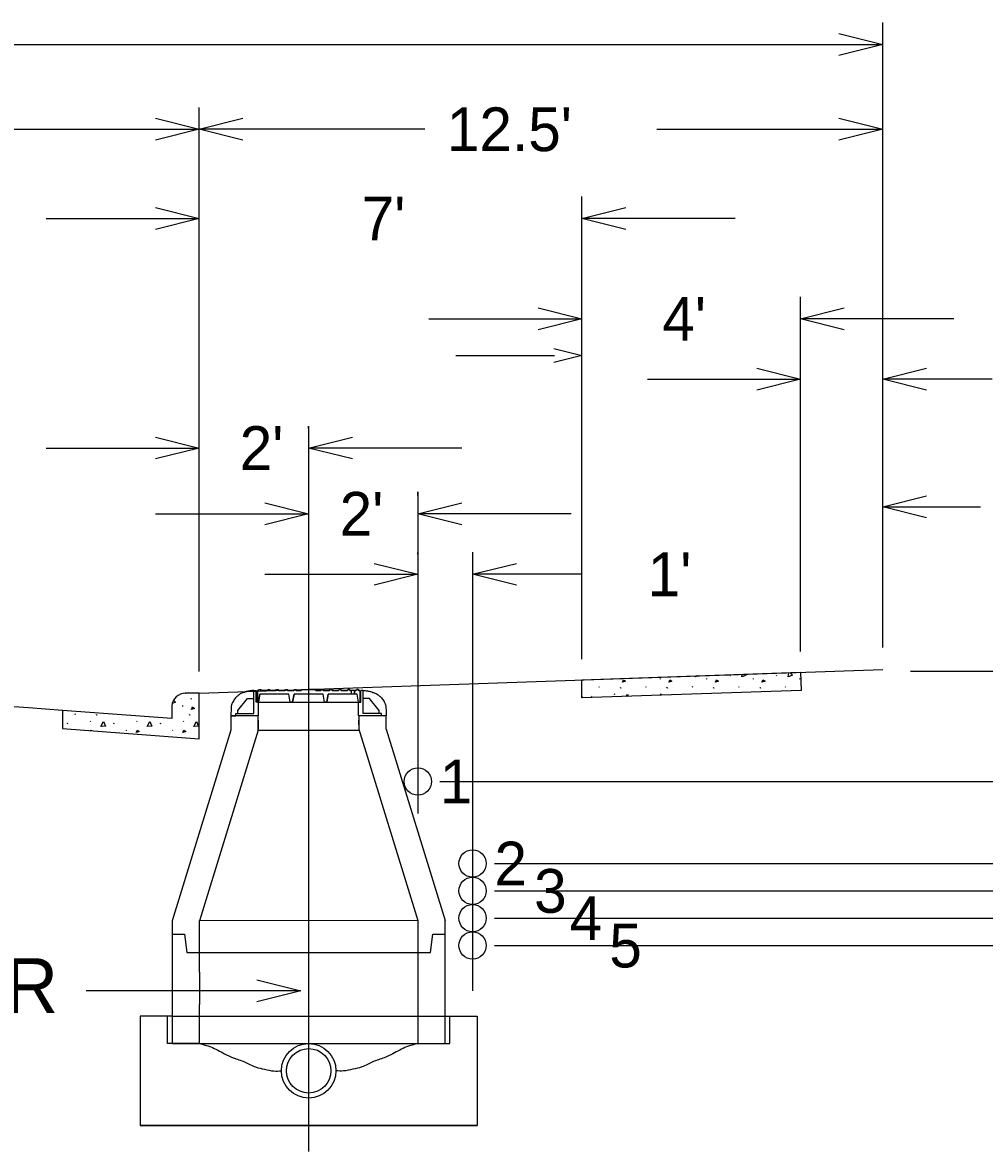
# Model space of a CAD drawing. Extents: x 524397 to 525117, y 3701341 to 3701821.
# Drawn here: x 524572.41 to 524607.59, y 3701671.5 to 3701712.8 of the extents above; entities that cross this region are included whole.
import ezdxf

# ---------------------------------------------------------------- set-up
doc = ezdxf.new("R2010")
doc.units = 0
doc.layers.add('Level 11', color=7, linetype='Continuous')

msp = doc.modelspace()

# ---------------------------------------------------------------- linework, layer by layer
at = {"layer": 'Level 11'}
for p, q in [((524603.871, 3701689.934), (524603.871, 3701712.797)), ((524542.077, 3701711.996), (524603.871, 3701711.996)), ((524578.871, 3701689.06), (524578.871, 3701709.694)), ((524603.871, 3701689.934), (524603.871, 3701709.694)), ((524536.524, 3701708.893), (524578.871, 3701708.893)), ((524587.129, 3701708.893), (524578.871, 3701708.893)), ((524595.613, 3701708.893), (524603.871, 3701708.893)), ((524578.871, 3701689.06), (524578.871, 3701706.43)), ((524578.871, 3701689.861), (524578.871, 3701706.43)), ((524592.871, 3701689.514), (524592.871, 3701706.43)), ((524577.27, 3701706.029), (524578.871, 3701705.629)), ((524577.27, 3701706.029), (524578.871, 3701705.629)), ((524592.871, 3701705.629), (524594.472, 3701706.029)), ((524573.267, 3701705.629), (524578.871, 3701705.629)), ((524578.871, 3701705.629), (524577.27, 3701705.229)), ((524578.871, 3701705.629), (524577.27, 3701705.229)), ((524598.475, 3701705.629), (524592.871, 3701705.629)), ((524594.472, 3701705.229), (524592.871, 3701705.629)), ((524592.871, 3701689.514), (524592.871, 3701702.759)), ((524600.866, 3701689.793), (524600.866, 3701702.759)), ((524591.27, 3701702.359), (524592.871, 3701701.959)), ((524600.866, 3701701.959), (524602.467, 3701702.359)), ((524587.267, 3701701.959), (524592.871, 3701701.959)), ((524592.871, 3701701.959), (524591.27, 3701701.559)), ((524606.47, 3701701.959), (524600.866, 3701701.959)), ((524602.467, 3701701.559), (524600.866, 3701701.959)), ((524591.84, 3701700.877), (524592.871, 3701700.619)), ((524588.262, 3701700.619), (524591.871, 3701700.619)), ((524592.871, 3701700.619), (524591.84, 3701700.362)), ((524600.866, 3701689.793), (524600.866, 3701700.554)), ((524603.871, 3701690.379), (524603.871, 3701700.554)), ((524599.265, 3701700.154), (524600.866, 3701699.754)), ((524603.871, 3701699.754), (524605.472, 3701700.154)), ((524595.263, 3701699.754), (524600.866, 3701699.754)), ((524600.866, 3701699.754), (524599.265, 3701699.354)), ((524607.874, 3701699.754), (524603.871, 3701699.754)), ((524605.472, 3701699.354), (524603.871, 3701699.754)), ((524578.871, 3701689.861), (524578.871, 3701698.033)), ((524582.871, 3701698.034), (524582.871, 3701671.502)), ((524582.871, 3701697.942), (524582.871, 3701698.033)), ((524577.27, 3701697.633), (524578.871, 3701697.233)), ((524582.871, 3701697.233), (524584.472, 3701697.633)), ((524573.267, 3701697.233), (524578.871, 3701697.233)), ((524578.871, 3701697.233), (524577.27, 3701696.833)), ((524588.475, 3701697.233), (524582.871, 3701697.233)), ((524584.472, 3701696.833), (524582.871, 3701697.233)), ((524586.871, 3701695.628), (524586.871, 3701695.061)), ((524586.871, 3701695.628), (524586.871, 3701683.862)), ((524586.871, 3701695.502), (524586.871, 3701695.627)), ((524603.875, 3701695.082), (524605.476, 3701695.483)), ((524581.27, 3701695.227), (524582.871, 3701694.827)), ((524586.871, 3701694.827), (524588.472, 3701695.227)), ((524603.875, 3701695.082), (524607.443, 3701695.082)), ((524605.476, 3701694.682), (524603.875, 3701695.082)), ((524577.267, 3701694.827), (524582.871, 3701694.827)), ((524582.871, 3701694.827), (524581.27, 3701694.427)), ((524592.475, 3701694.827), (524586.871, 3701694.827)), ((524588.472, 3701694.427), (524586.871, 3701694.827)), ((524582.871, 3701694.141), (524582.871, 3701694.027)), ((524586.871, 3701693.342), (524586.871, 3701693.414)), ((524588.871, 3701693.428), (524588.871, 3701677.373)), ((524585.27, 3701693.014), (524586.871, 3701692.613)), ((524588.871, 3701692.613), (524590.472, 3701693.014)), ((524581.267, 3701692.613), (524586.871, 3701692.613)), ((524586.871, 3701692.613), (524585.27, 3701692.213)), ((524588.871, 3701692.627), (524588.871, 3701691.813)), ((524592.874, 3701692.613), (524588.871, 3701692.613)), ((524590.472, 3701692.213), (524588.871, 3701692.613)), ((524578.871, 3701688.26), (524603.871, 3701689.133)), ((524592.871, 3701688.749), (524600.866, 3701689.029)), ((524595.726, 3701688.806), (524595.73, 3701688.774)), ((524597.428, 3701688.806), (524597.431, 3701688.774)), ((524598.285, 3701688.895), (524598.299, 3701688.927)), ((524599.129, 3701688.806), (524599.133, 3701688.774)), ((524599.986, 3701688.895), (524600.001, 3701688.927)), ((524600.831, 3701688.806), (524600.834, 3701688.774)), ((524600.866, 3701689.029), (524600.889, 3701688.369)), ((524610.833, 3701689.063), (524604.887, 3701689.063)), ((524581.039, 3701688.358), (524581.054, 3701688.4)), ((524581.039, 3701688.358), (524581.054, 3701688.4)), ((524581.054, 3701688.4), (524581.117, 3701688.4)), ((524581.054, 3701688.4), (524581.117, 3701688.4)), ((524581.132, 3701688.358), (524581.117, 3701688.4)), ((524581.117, 3701688.4), (524581.132, 3701688.358)), ((524581.363, 3701688.358), (524581.378, 3701688.4)), ((524581.363, 3701688.358), (524581.378, 3701688.4)), ((524581.378, 3701688.4), (524581.438, 3701688.4)), ((524581.378, 3701688.4), (524581.438, 3701688.4)), ((524581.453, 3701688.358), (524581.438, 3701688.4)), ((524581.438, 3701688.4), (524581.453, 3701688.358)), ((524581.679, 3701688.358), (524581.694, 3701688.4)), ((524581.679, 3701688.358), (524581.694, 3701688.4)), ((524581.694, 3701688.4), (524581.762, 3701688.4)), ((524581.694, 3701688.4), (524581.762, 3701688.4)), ((524581.777, 3701688.358), (524581.762, 3701688.4)), ((524581.762, 3701688.4), (524581.777, 3701688.358)), ((524582.006, 3701688.358), (524582.022, 3701688.4)), ((524582.006, 3701688.358), (524582.022, 3701688.4)), ((524582.022, 3701688.4), (524582.087, 3701688.4)), ((524582.022, 3701688.4), (524582.087, 3701688.4)), ((524582.102, 3701688.358), (524582.087, 3701688.4)), ((524582.087, 3701688.4), (524582.102, 3701688.358)), ((524582.329, 3701688.358), (524582.344, 3701688.4)), ((524582.329, 3701688.358), (524582.344, 3701688.4)), ((524582.344, 3701688.4), (524582.402, 3701688.4)), ((524582.344, 3701688.4), (524582.402, 3701688.4)), ((524582.418, 3701688.358), (524582.402, 3701688.4)), ((524582.402, 3701688.4), (524582.418, 3701688.358)), ((524582.604, 3701688.358), (524582.62, 3701688.4)), ((524582.604, 3701688.358), (524582.62, 3701688.4)), ((524582.62, 3701688.4), (524582.87, 3701688.4)), ((524582.62, 3701688.4), (524583.122, 3701688.4)), ((524583.122, 3701688.4), (524582.87, 3701688.4)), ((524583.137, 3701688.358), (524583.122, 3701688.4)), ((524583.122, 3701688.4), (524583.137, 3701688.358)), ((524583.324, 3701688.358), (524583.339, 3701688.4)), ((524583.324, 3701688.358), (524583.339, 3701688.4)), ((524583.397, 3701688.4), (524583.339, 3701688.4)), ((524583.339, 3701688.4), (524583.397, 3701688.4)), ((524583.412, 3701688.358), (524583.397, 3701688.4)), ((524583.397, 3701688.4), (524583.412, 3701688.358)), ((524583.639, 3701688.358), (524583.655, 3701688.4)), ((524583.639, 3701688.358), (524583.655, 3701688.4)), ((524583.72, 3701688.4), (524583.655, 3701688.4)), ((524583.655, 3701688.4), (524583.72, 3701688.4)), ((524583.735, 3701688.358), (524583.72, 3701688.4)), ((524583.72, 3701688.4), (524583.735, 3701688.358)), ((524583.964, 3701688.358), (524583.979, 3701688.4)), ((524583.964, 3701688.358), (524583.979, 3701688.4)), ((524584.047, 3701688.4), (524583.979, 3701688.4)), ((524583.979, 3701688.4), (524584.047, 3701688.4)), ((524584.062, 3701688.358), (524584.047, 3701688.4)), ((524584.047, 3701688.4), (524584.062, 3701688.358)), ((524584.289, 3701688.358), (524584.303, 3701688.4)), ((524584.289, 3701688.358), (524584.303, 3701688.4)), ((524584.363, 3701688.4), (524584.303, 3701688.4)), ((524584.303, 3701688.4), (524584.363, 3701688.4)), ((524584.378, 3701688.358), (524584.363, 3701688.4)), ((524584.363, 3701688.4), (524584.378, 3701688.358)), ((524584.609, 3701688.358), (524584.625, 3701688.4)), ((524584.609, 3701688.358), (524584.625, 3701688.4)), ((524584.687, 3701688.4), (524584.625, 3701688.4)), ((524584.625, 3701688.4), (524584.687, 3701688.4)), ((524584.702, 3701688.358), (524584.687, 3701688.4)), ((524584.687, 3701688.4), (524584.702, 3701688.358)), ((524592.871, 3701688.089), (524592.871, 3701688.749)), ((524593.504, 3701688.483), (524593.518, 3701688.515)), ((524594.027, 3701688.79), (524594.028, 3701688.774)), ((524594.267, 3701688.483), (524594.281, 3701688.462)), ((524594.281, 3701688.475), (524594.296, 3701688.454)), ((524595.205, 3701688.483), (524595.219, 3701688.515)), ((524595.969, 3701688.483), (524595.983, 3701688.462)), ((524595.983, 3701688.475), (524595.997, 3701688.454)), ((524596.907, 3701688.483), (524596.921, 3701688.515)), ((524597.67, 3701688.483), (524597.684, 3701688.462)), ((524597.684, 3701688.475), (524597.699, 3701688.454)), ((524598.608, 3701688.483), (524598.622, 3701688.515)), ((524599.372, 3701688.483), (524599.386, 3701688.462)), ((524599.386, 3701688.475), (524599.4, 3701688.454)), ((524600.31, 3701688.483), (524600.324, 3701688.515)), ((524578.871, 3701688.26), (524578.358, 3701688.26)), ((524578.358, 3701688.26), (524578.371, 3701688.26)), ((524578.871, 3701688.26), (524578.358, 3701688.26)), ((524578.358, 3701688.26), (524578.371, 3701688.26)), ((524578.577, 3701688.047), (524578.591, 3701688.078)), ((524578.577, 3701688.047), (524578.591, 3701688.078)), ((524578.871, 3701686.598), (524578.871, 3701688.26)), ((524578.871, 3701686.598), (524578.871, 3701688.26)), ((524580.289, 3701687.63), (524580.639, 3701688.067)), ((524580.639, 3701688.067), (524580.872, 3701688.067)), ((524580.872, 3701688.358), (524580.872, 3701688.358)), ((524580.872, 3701688.358), (524580.955, 3701688.358)), ((524580.872, 3701688.067), (524580.872, 3701688.358)), ((524580.872, 3701687.525), (524580.872, 3701688.067)), ((524580.955, 3701687.942), (524580.955, 3701688.358)), ((524580.997, 3701688.358), (524580.997, 3701687.942)), ((524581.039, 3701688.358), (524580.997, 3701688.358)), ((524580.997, 3701688.358), (524581.039, 3701688.358)), ((524580.997, 3701687.942), (524580.997, 3701688.358)), ((524581.038, 3701687.942), (524581.09, 3701688.233)), ((524581.09, 3701688.233), (524581.038, 3701687.942)), ((524582.153, 3701688.233), (524581.09, 3701688.233)), ((524582.153, 3701688.233), (524581.09, 3701688.233)), ((524581.363, 3701688.358), (524581.132, 3701688.358)), ((524581.132, 3701688.358), (524581.363, 3701688.358)), ((524581.679, 3701688.358), (524581.453, 3701688.358)), ((524581.453, 3701688.358), (524581.679, 3701688.358)), ((524582.006, 3701688.358), (524581.777, 3701688.358)), ((524581.777, 3701688.358), (524582.006, 3701688.358)), ((524582.329, 3701688.358), (524582.102, 3701688.358)), ((524582.102, 3701688.358), (524582.329, 3701688.358)), ((524582.204, 3701687.942), (524582.153, 3701688.233)), ((524582.204, 3701687.942), (524582.153, 3701688.233)), ((524582.288, 3701687.942), (524582.339, 3701688.233)), ((524582.339, 3701688.233), (524582.288, 3701687.942)), ((524583.402, 3701688.233), (524582.339, 3701688.233)), ((524583.402, 3701688.233), (524582.339, 3701688.233)), ((524582.604, 3701688.358), (524582.418, 3701688.358)), ((524582.418, 3701688.358), (524582.604, 3701688.358)), ((524583.324, 3701688.358), (524583.137, 3701688.358)), ((524583.137, 3701688.358), (524583.324, 3701688.358)), ((524583.454, 3701687.942), (524583.402, 3701688.233)), ((524583.454, 3701687.942), (524583.402, 3701688.233)), ((524583.639, 3701688.358), (524583.412, 3701688.358)), ((524583.412, 3701688.358), (524583.639, 3701688.358)), ((524583.537, 3701687.942), (524583.588, 3701688.233)), ((524583.588, 3701688.233), (524583.537, 3701687.942)), ((524584.651, 3701688.233), (524583.588, 3701688.233)), ((524584.432, 3701688.233), (524583.588, 3701688.233)), ((524583.964, 3701688.358), (524583.735, 3701688.358)), ((524583.735, 3701688.358), (524583.964, 3701688.358)), ((524584.289, 3701688.358), (524584.062, 3701688.358)), ((524584.062, 3701688.358), (524584.289, 3701688.358)), ((524584.609, 3701688.358), (524584.378, 3701688.358)), ((524584.378, 3701688.358), (524584.432, 3701688.358)), ((524584.432, 3701688.358), (524584.432, 3701688.233)), ((524584.432, 3701688.358), (524584.432, 3701688.233)), ((524584.557, 3701688.358), (524584.557, 3701688.233)), ((524584.557, 3701688.358), (524584.609, 3701688.358)), ((524584.557, 3701688.233), (524584.557, 3701688.358)), ((524584.651, 3701688.233), (524584.557, 3701688.233)), ((524584.703, 3701687.942), (524584.651, 3701688.233)), ((524584.703, 3701687.942), (524584.651, 3701688.233)), ((524584.744, 3701688.358), (524584.702, 3701688.358)), ((524584.702, 3701688.358), (524584.744, 3701688.358)), ((524584.744, 3701688.358), (524584.744, 3701687.942)), ((524584.744, 3701688.358), (524584.744, 3701687.942)), ((524584.786, 3701687.942), (524584.786, 3701688.358)), ((524584.869, 3701688.358), (524584.786, 3701688.358)), ((524584.869, 3701688.067), (524584.869, 3701688.358)), ((524584.869, 3701687.525), (524584.869, 3701688.067)), ((524585.102, 3701688.067), (524584.869, 3701688.067)), ((524585.452, 3701687.63), (524585.102, 3701688.067)), ((524600.889, 3701688.369), (524592.871, 3701688.089)), ((524593.216, 3701688.138), (524593.23, 3701688.17)), ((524594.058, 3701688.22), (524594.072, 3701688.252)), ((524594.927, 3701688.161), (524594.932, 3701688.17)), ((524595.759, 3701688.22), (524595.773, 3701688.252)), ((524597.474, 3701688.25), (524597.475, 3701688.252)), ((524577.871, 3701687.335), (524573.871, 3701687.637)), ((524573.871, 3701687.637), (524573.871, 3701686.976)), ((524577.871, 3701687.335), (524573.871, 3701687.637)), ((524573.871, 3701687.637), (524573.871, 3701686.976)), ((524577.871, 3701687.798), (524577.871, 3701687.335)), ((524577.871, 3701687.798), (524577.871, 3701687.335)), ((524578.26, 3701687.812), (524578.263, 3701687.78)), ((524578.26, 3701687.812), (524578.263, 3701687.78)), ((524580.289, 3701687.525), (524580.289, 3701687.63)), ((524581.038, 3701687.942), (524580.955, 3701687.942)), ((524580.997, 3701687.942), (524584.744, 3701687.942)), ((524581.038, 3701687.942), (524580.997, 3701687.942)), ((524581.038, 3701687.442), (524581.038, 3701687.942)), ((524582.288, 3701687.942), (524582.204, 3701687.942)), ((524583.537, 3701687.942), (524583.454, 3701687.942)), ((524584.703, 3701687.442), (524584.703, 3701687.942)), ((524584.703, 3701687.942), (524584.786, 3701687.942)), ((524584.744, 3701687.942), (524584.703, 3701687.942)), ((524585.452, 3701687.525), (524585.452, 3701687.63)), ((524574.048, 3701687.144), (524574.062, 3701687.176)), ((524574.048, 3701687.144), (524574.062, 3701687.176)), ((524574.336, 3701687.489), (524574.35, 3701687.521)), ((524574.336, 3701687.489), (524574.35, 3701687.521)), ((524574.89, 3701687.226), (524574.904, 3701687.258)), ((524574.89, 3701687.226), (524574.904, 3701687.258)), ((524575.099, 3701687.489), (524575.113, 3701687.468)), ((524575.099, 3701687.489), (524575.113, 3701687.468)), ((524575.113, 3701687.481), (524575.128, 3701687.459)), ((524575.113, 3701687.481), (524575.128, 3701687.459)), ((524575.749, 3701687.144), (524575.764, 3701687.176)), ((524575.749, 3701687.144), (524575.764, 3701687.176)), ((524576.591, 3701687.226), (524576.605, 3701687.258)), ((524576.591, 3701687.226), (524576.605, 3701687.258)), ((524577.451, 3701687.144), (524577.465, 3701687.176)), ((524577.451, 3701687.144), (524577.465, 3701687.176)), ((524578.293, 3701687.226), (524578.307, 3701687.258)), ((524578.293, 3701687.226), (524578.307, 3701687.258)), ((524578.502, 3701687.489), (524578.516, 3701687.468)), ((524578.502, 3701687.489), (524578.516, 3701687.468)), ((524578.516, 3701687.481), (524578.531, 3701687.459)), ((524578.516, 3701687.481), (524578.531, 3701687.459)), ((524580.028, 3701687.442), (524580.028, 3701686.909)), ((524581.038, 3701687.442), (524580.028, 3701687.442)), ((524580.028, 3701687.442), (524580.205, 3701687.442)), ((524580.205, 3701687.442), (524580.205, 3701687.525)), ((524580.205, 3701687.525), (524580.289, 3701687.525)), ((524580.289, 3701687.525), (524580.872, 3701687.525)), ((524581.028, 3701686.909), (524581.028, 3701687.442)), ((524581.028, 3701687.276), (524581.028, 3701686.949)), ((524585.713, 3701687.442), (524584.703, 3701687.442)), ((524584.713, 3701687.442), (524584.713, 3701686.943)), ((524584.713, 3701687.109), (524584.713, 3701687.283)), ((524585.713, 3701687.442), (524584.714, 3701687.442)), ((524585.452, 3701687.525), (524584.869, 3701687.525)), ((524585.535, 3701687.525), (524585.452, 3701687.525)), ((524585.535, 3701687.442), (524585.535, 3701687.525)), ((524585.713, 3701687.442), (524585.535, 3701687.442)), ((524585.713, 3701686.943), (524585.713, 3701687.442)), ((524573.871, 3701686.976), (524578.871, 3701686.598)), ((524573.871, 3701686.976), (524578.871, 3701686.598)), ((524576.193, 3701686.917), (524576.208, 3701686.895)), ((524576.193, 3701686.917), (524576.208, 3701686.895)), ((524580.028, 3701686.909), (524577.878, 3701679.942)), ((524577.895, 3701686.917), (524577.909, 3701686.895)), ((524577.895, 3701686.917), (524577.909, 3701686.895)), ((524581.028, 3701686.909), (524578.877, 3701679.942)), ((524581.028, 3701686.909), (524584.713, 3701686.909)), ((524584.713, 3701686.943), (524586.873, 3701679.947)), ((524585.713, 3701686.943), (524587.872, 3701679.947)), ((524587.671, 3701685.033), (524617.96, 3701685.033)), ((524589.671, 3701682.033), (524620.485, 3701682.033)), ((524589.671, 3701681.033), (524622.729, 3701681.033)), ((524577.878, 3701679.942), (524577.878, 3701678.781)), ((524586.873, 3701679.946), (524578.877, 3701679.942)), ((524578.877, 3701678.781), (524578.877, 3701679.942)), ((524586.873, 3701679.947), (524586.873, 3701678.781)), ((524586.873, 3701679.947), (524586.873, 3701679.447)), ((524587.872, 3701679.447), (524587.872, 3701679.947)), ((524587.872, 3701679.447), (524587.872, 3701679.947)), ((524589.671, 3701680.033), (524624.974, 3701680.033)), ((524577.878, 3701679.649), (524577.878, 3701679.447)), ((524577.878, 3701679.447), (524578.336, 3701679.447)), ((524577.878, 3701679.447), (524578.336, 3701679.447)), ((524577.878, 3701679.447), (524577.878, 3701678.06)), ((524578.336, 3701679.447), (524578.419, 3701678.781)), ((524578.336, 3701679.447), (524578.419, 3701678.781)), ((524578.877, 3701679.447), (524578.877, 3701679.649)), ((524578.877, 3701678.06), (524578.877, 3701679.447)), ((524586.873, 3701679.649), (524586.873, 3701679.447)), ((524586.873, 3701679.649), (524586.873, 3701679.447)), ((524586.873, 3701679.447), (524586.873, 3701675.449)), ((524586.873, 3701679.447), (524586.873, 3701675.449)), ((524587.331, 3701678.781), (524587.414, 3701679.447)), ((524587.331, 3701678.781), (524587.414, 3701679.447)), ((524587.414, 3701679.447), (524587.872, 3701679.447)), ((524587.414, 3701679.447), (524587.872, 3701679.447)), ((524587.414, 3701679.447), (524587.872, 3701679.447)), ((524587.872, 3701675.449), (524587.872, 3701679.649)), ((524587.872, 3701678.781), (524587.872, 3701679.447)), ((524577.878, 3701679.059), (524577.878, 3701675.449)), ((524589.671, 3701679.033), (524627.499, 3701679.033)), ((524578.419, 3701678.781), (524578.877, 3701678.781)), ((524578.419, 3701678.781), (524578.877, 3701678.781)), ((524578.877, 3701678.781), (524586.873, 3701678.781)), ((524578.877, 3701678.781), (524586.873, 3701678.781)), ((524586.873, 3701678.781), (524587.331, 3701678.781)), ((524586.873, 3701678.781), (524587.331, 3701678.781)), ((524578.877, 3701678.06), (524578.877, 3701676.875)), ((524580.981, 3701677.775), (524582.582, 3701677.375)), ((524582.582, 3701677.375), (524574.74, 3701677.375)), ((524582.582, 3701677.375), (524580.981, 3701676.975)), ((524578.877, 3701675.449), (524578.877, 3701676.875)), ((524577.878, 3701676.449), (524576.712, 3701676.449)), ((524576.712, 3701676.449), (524576.712, 3701672.451)), ((524577.712, 3701675.449), (524577.712, 3701676.449)), ((524577.878, 3701676.449), (524587.872, 3701676.449)), ((524587.872, 3701676.449), (524589.038, 3701676.449)), ((524588.039, 3701675.449), (524588.039, 3701676.449)), ((524589.038, 3701676.449), (524589.038, 3701672.451)), ((524577.878, 3701675.449), (524577.712, 3701675.449)), ((524577.878, 3701675.449), (524577.712, 3701675.449)), ((524577.878, 3701675.449), (524578.877, 3701675.449)), ((524578.877, 3701675.449), (524577.878, 3701675.449)), ((524578.877, 3701675.449), (524577.878, 3701675.449)), ((524578.877, 3701675.449), (524586.873, 3701675.449)), ((524586.873, 3701675.449), (524587.872, 3701675.449)), ((524586.873, 3701675.449), (524587.872, 3701675.449)), ((524587.872, 3701675.449), (524588.039, 3701675.449)), ((524589.038, 3701672.451), (524576.712, 3701672.451)), ((524576.712, 3701672.451), (524589.038, 3701672.451))]:
    msp.add_line(p, q, dxfattribs=at)
for points in [[(524602.27, 3701712.397), (524603.871, 3701711.996), (524602.27, 3701711.596)], [(524577.27, 3701709.294), (524578.871, 3701708.893), (524577.27, 3701708.493)], [(524580.472, 3701708.493), (524578.871, 3701708.893), (524580.472, 3701709.294)], [(524602.27, 3701709.294), (524603.871, 3701708.893), (524602.27, 3701708.493)], [(524597.015, 3701688.859), (524597.02, 3701688.894)], [(524597.099, 3701688.897), (524597.019, 3701688.86)], [(524598.717, 3701688.859), (524598.73, 3701688.954)], [(524598.845, 3701688.958), (524598.872, 3701688.93), (524598.72, 3701688.86)], [(524600.418, 3701688.859), (524600.44, 3701689.014)], [(524600.491, 3701689.015), (524600.574, 3701688.93), (524600.422, 3701688.86)], [(524594.349, 3701688.668), (524594.392, 3701688.757), (524594.463, 3701688.703), (524594.349, 3701688.668)], [(524596.051, 3701688.668), (524596.093, 3701688.757), (524596.164, 3701688.703), (524596.051, 3701688.668)], [(524597.752, 3701688.668), (524597.795, 3701688.757), (524597.866, 3701688.703), (524597.752, 3701688.668)], [(524599.454, 3701688.668), (524599.496, 3701688.757), (524599.567, 3701688.703), (524599.454, 3701688.668)], [(524577.935, 3701688.006), (524578.003, 3701687.936), (524577.898, 3701687.887)], [(524577.935, 3701688.006), (524578.003, 3701687.936), (524577.898, 3701687.887)], [(524592.871, 3701688.137), (524592.892, 3701688.09)], [(524594.492, 3701688.146), (524594.534, 3701688.223), (524594.567, 3701688.148)], [(524596.226, 3701688.206), (524596.235, 3701688.223), (524596.243, 3701688.207)], [(524578.584, 3701687.674), (524578.627, 3701687.762), (524578.698, 3701687.709), (524578.584, 3701687.674)], [(524578.584, 3701687.674), (524578.627, 3701687.762), (524578.698, 3701687.709), (524578.584, 3701687.674)], [(524575.27, 3701687.048), (524575.366, 3701687.229), (524575.44, 3701687.062), (524575.273, 3701687.048)], [(524575.27, 3701687.048), (524575.366, 3701687.229), (524575.44, 3701687.062), (524575.273, 3701687.048)], [(524576.971, 3701687.048), (524577.067, 3701687.229), (524577.142, 3701687.062), (524576.975, 3701687.048)], [(524576.971, 3701687.048), (524577.067, 3701687.229), (524577.142, 3701687.062), (524576.975, 3701687.048)], [(524578.673, 3701687.048), (524578.769, 3701687.229), (524578.843, 3701687.062), (524578.676, 3701687.048)], [(524578.673, 3701687.048), (524578.769, 3701687.229), (524578.843, 3701687.062), (524578.676, 3701687.048)], [(524574.9, 3701686.898), (524574.907, 3701686.913), (524574.93, 3701686.896)], [(524574.9, 3701686.898), (524574.907, 3701686.913), (524574.93, 3701686.896)], [(524576.566, 3701686.824), (524576.609, 3701686.913), (524576.68, 3701686.86), (524576.566, 3701686.824)], [(524576.566, 3701686.824), (524576.609, 3701686.913), (524576.68, 3701686.86), (524576.566, 3701686.824)], [(524578.268, 3701686.824), (524578.31, 3701686.913), (524578.381, 3701686.86), (524578.268, 3701686.824)], [(524578.268, 3701686.824), (524578.31, 3701686.913), (524578.381, 3701686.86), (524578.268, 3701686.824)]]:
    msp.add_lwpolyline(points, dxfattribs=at)
for centre, radius in [((524586.871, 3701685.033), 0.5), ((524588.871, 3701682.033), 0.5), ((524588.871, 3701681.033), 0.5), ((524588.871, 3701680.033), 0.5), ((524588.871, 3701679.033), 0.5), ((524582.875, 3701674.45), 0.999), ((524582.875, 3701674.45), 0.814)]:
    msp.add_circle(centre, radius, dxfattribs=at)
for centre, radius, start, end in [((524533.871, 3701157.836), 531.309, 85.68236, 94.31764), ((524578.364, 3701687.766), 0.494, 89.2332, 176.2921), ((524578.364, 3701687.766), 0.494, 89.2332, 176.2921)]:
    msp.add_arc(centre, radius, start, end, dxfattribs=at)
for points in [[(524580.872, 3701688.358), (524580.799, 3701688.357), (524580.72, 3701688.347), (524580.651, 3701688.335), (524580.592, 3701688.323), (524580.528, 3701688.295), (524580.47, 3701688.282), (524580.327, 3701688.202), (524580.223, 3701688.116), (524580.132, 3701687.998), (524580.056, 3701687.834), (524580.035, 3701687.601), (524580.028, 3701687.442)], [(524584.869, 3701688.358), (524584.942, 3701688.357), (524585.021, 3701688.347), (524585.09, 3701688.335), (524585.149, 3701688.323), (524585.213, 3701688.295), (524585.272, 3701688.282), (524585.415, 3701688.202), (524585.518, 3701688.116), (524585.609, 3701687.998), (524585.685, 3701687.834), (524585.706, 3701687.601), (524585.713, 3701687.442)], [(524578.877, 3701675.449), (524579.292, 3701675.325), (524579.795, 3701675.073), (524580.11, 3701674.927), (524580.53, 3701674.78), (524580.929, 3701674.591), (524581.265, 3701674.507), (524581.601, 3701674.445), (524581.876, 3701674.45)], [(524586.873, 3701675.449), (524586.459, 3701675.325), (524585.955, 3701675.073), (524585.64, 3701674.927), (524585.22, 3701674.78), (524584.821, 3701674.591), (524584.485, 3701674.507), (524584.149, 3701674.445), (524583.874, 3701674.45)]]:
    msp.add_spline(points, degree=3, dxfattribs=at)

# ---------------------------------------------------------------- texts
for s, height, p in [("12.5'", 1.601, (524587.929, 3701708.093)), ("7'", 1.601, (524584.812, 3701704.829)), ("4'", 1.601, (524595.81, 3701701.158)), ("2'", 1.601, (524580.351, 3701696.432)), ("2'", 1.601, (524584.007, 3701694.026)), ("1'", 1.601, (524595.275, 3701691.813)), ('1', 1.601, (524587.671, 3701684.232)), ('2', 1.601, (524589.671, 3701681.232)), ('3', 1.601, (524591.121, 3701680.232)), ('4', 1.601, (524592.42, 3701679.232)), ('5', 1.601, (524593.87, 3701678.232)), ('SEWER', 2, (524563.901, 3701676.57))]:
    msp.add_text(s, height=height, dxfattribs=at).set_placement(p)

doc.saveas('drawing.dxf')
